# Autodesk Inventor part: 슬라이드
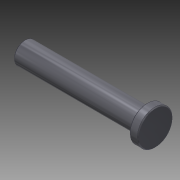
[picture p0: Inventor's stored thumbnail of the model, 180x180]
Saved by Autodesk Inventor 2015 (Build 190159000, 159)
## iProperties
Created: 2015-10
Part Number: 슬라이드
Document SubType Name: Modeling
Designer: mdu
Density: 1 g/cm^3
Material: 강철, 연강
Appearance: 진회색
Author: mdu
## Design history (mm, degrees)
sketch "스케치1"
  geometry: L1 (-75, 162)-(-75, 58) reference; L2 (-128, 110)-(22, 110); L3 (-128, 110)-(-128, 122.5); L4 (-128, 122.5)-(12, 122.5); L5 (12, 122.5)-(12, 130); L6 (12, 130)-(22, 130); L7 (22, 130)-(22, 110); 2 further points
  constraints: 12 end point, 3 parallel, 3 perpendicular, 1 midpoint, 1 point on line
  dimensions: "d0" = 40 diameter of L6 L2; "d1" = 25 diameter of L4 L2; "d2" = 10 distance of L5.end L6.end; "d3" = 150 distance of L2.start L2.end; "d4" = 53 distance between parallel lines of L3 L1
revolve "회전1" sketch "스케치1" stored, may be unused: angle "d5" = 90 deg
hole "구멍1" diameter "d11" = 10.106; stored, may be unused: countersink angle "d15" = 90 deg, drill point angle "d17" = 118 deg; dims "d12" = 22, "d13" = 4, "d14" = 2, "d16" = 25, "d18" = 10, "d19" = 10
chamfer "모따기1" distance "d6" = 1; stored, may be unused: second distance "d7" = 2, angle "d8" = 45 deg
node "솔리드1"
node "참조1"
